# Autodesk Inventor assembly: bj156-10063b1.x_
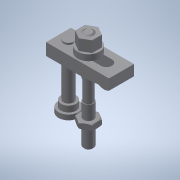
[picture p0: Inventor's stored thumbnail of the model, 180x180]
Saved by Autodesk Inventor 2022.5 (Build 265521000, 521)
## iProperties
Part Number: bj156-10063b1.x_
Material: 一般
Document SubType Name: Assembly
Designer: ImaoCorp
Sending System: SOLIDWORKS 2017-2017317
MC: AMD64
MC_MODEL: Intel64 Family 6 Model 60 Stepping 3, GenuineIntel
OS: Windows_NT
FRU: Parasolid Version 29.0, build 201,  4-17-2017
FORMAT: text
GUISE: transmit
KEY: bj156-10063b1
FILE: bj156-10063b1.x_t
DATE: Fri Mar 15 10:21:24 2019
Author: ImaoCorp
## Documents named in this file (6)
- X:\14_SW2022-Inv2022\00_全2023-1023新製品(TCC)まで\b\bj156-10063b1\BJ156-10063B1.iam
- X:\14_SW2022-Inv2022\00_全2023-1023新製品(TCC)まで\b\bj156-10063b1\bj156-10063b1_01.ipt
- X:\14_SW2022-Inv2022\00_全2023-1023新製品(TCC)まで\b\bj156-10063b1\bj156-10063b1_02.ipt
- X:\14_SW2022-Inv2022\00_全2023-1023新製品(TCC)まで\b\bj156-10063b1\bj156-10063b1_03.ipt
- X:\14_SW2022-Inv2022\00_全2023-1023新製品(TCC)まで\b\bj156-10063b1\bj156-10063b1_04.ipt
- X:\14_SW2022-Inv2022\00_全2023-1023新製品(TCC)まで\b\bj156-10063b1\bj156-10063b1_05.ipt
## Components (5 placed, 5 different names)
1. bj156-10063b1_01
2. bj156-10063b1_02
3. bj156-10063b1_03
4. bj156-10063b1_04
5. bj156-10063b1_05
